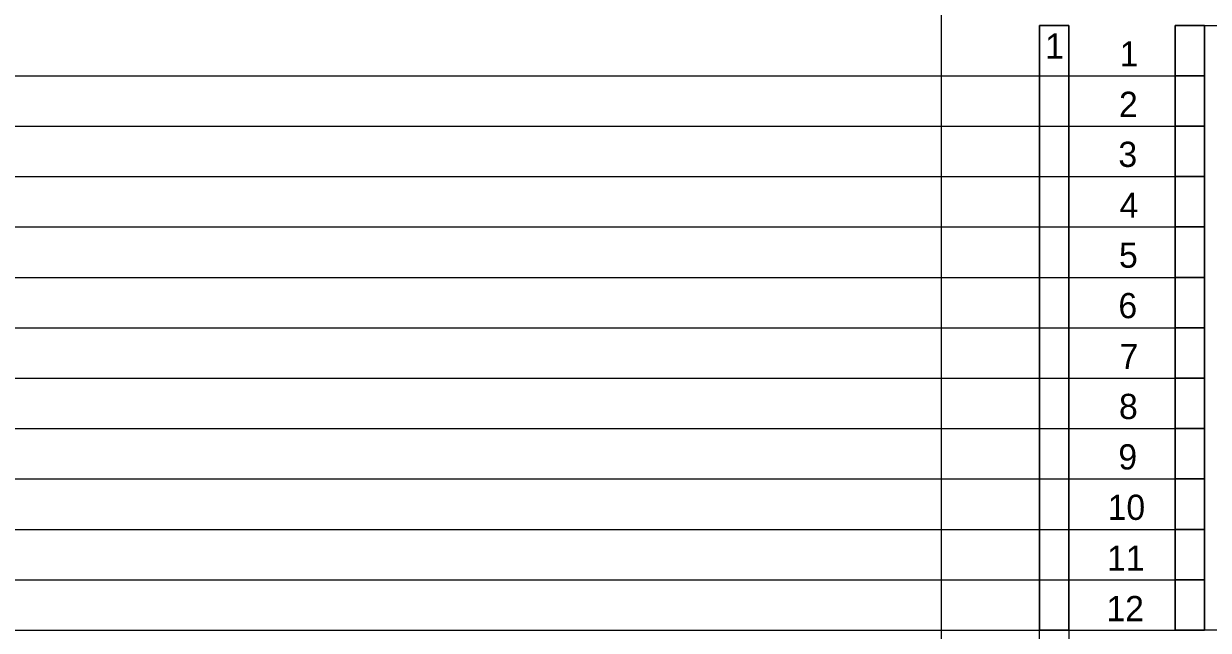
# Model space of a CAD drawing. Extents: x 1901 to 2519, y -3585 to -3154.
# Drawn here: x 2166.7 to 2249.4, y -3245.2 to -3202.9 of the extents above; entities that cross this region are included whole.
import ezdxf

# ---------------------------------------------------------------- set-up
doc = ezdxf.new("R2010")
doc.units = 0
doc.layers.add('rozvláknění', color=7, linetype='Continuous')

msp = doc.modelspace()

# ---------------------------------------------------------------- linework, layer by layer
at = {"layer": 'rozvláknění'}
for p, q in [((2115.435, -3206.527), (2247.063, -3206.526)), ((2115.435, -3210.045), (2247.063, -3210.044)), ((2115.435, -3213.563), (2247.063, -3213.562)), ((2115.435, -3217.081), (2247.063, -3217.08)), ((2115.435, -3220.599), (2247.063, -3220.598)), ((2115.435, -3224.117), (2247.063, -3224.117)), ((2115.435, -3227.636), (2247.063, -3227.635)), ((2115.435, -3231.154), (2247.063, -3231.153)), ((2115.435, -3234.672), (2247.063, -3234.671)), ((2115.435, -3238.19), (2247.063, -3238.189)), ((2115.435, -3241.708), (2247.063, -3241.708)), ((2115.435, -3245.227), (2247.063, -3245.226))]:
    msp.add_line(p, q, dxfattribs=at)
for points in [[(2230.76, -3165.344), (2269.157, -3165.343), (2269.157, -3379.277), (2230.76, -3379.277)], [(2239.641, -3287.48), (2237.6, -3287.48), (2237.6, -3203.007), (2239.641, -3203.007)], [(2239.641, -3245.226), (2237.6, -3245.226), (2237.6, -3203.007), (2239.641, -3203.007)], [(2247.063, -3203.007), (2249.104, -3203.007), (2249.104, -3206.526), (2247.063, -3206.526)], [(2247.063, -3203.007), (2249.104, -3203.007), (2249.104, -3206.526), (2247.063, -3206.526)], [(2249.104, -3203.007), (2251.891, -3203.007), (2251.891, -3245.222), (2249.104, -3245.222)], [(2247.063, -3206.526), (2249.104, -3206.526), (2249.104, -3210.044), (2247.063, -3210.044)], [(2247.063, -3206.526), (2249.104, -3206.526), (2249.104, -3210.044), (2247.063, -3210.044)], [(2247.063, -3210.044), (2249.104, -3210.044), (2249.104, -3213.562), (2247.063, -3213.562)], [(2247.063, -3210.044), (2249.104, -3210.044), (2249.104, -3213.562), (2247.063, -3213.562)], [(2247.063, -3213.562), (2249.104, -3213.562), (2249.104, -3217.08), (2247.063, -3217.08)], [(2247.063, -3213.562), (2249.104, -3213.562), (2249.104, -3217.08), (2247.063, -3217.08)], [(2247.063, -3217.08), (2249.104, -3217.08), (2249.104, -3220.598), (2247.063, -3220.598)], [(2247.063, -3217.08), (2249.104, -3217.08), (2249.104, -3220.598), (2247.063, -3220.598)], [(2247.063, -3220.598), (2249.104, -3220.598), (2249.104, -3224.117), (2247.063, -3224.117)], [(2247.063, -3220.598), (2249.104, -3220.598), (2249.104, -3224.117), (2247.063, -3224.117)], [(2247.063, -3224.117), (2249.104, -3224.117), (2249.104, -3227.635), (2247.063, -3227.635)], [(2247.063, -3224.117), (2249.104, -3224.117), (2249.104, -3227.635), (2247.063, -3227.635)], [(2247.063, -3227.635), (2249.104, -3227.635), (2249.104, -3231.153), (2247.063, -3231.153)], [(2247.063, -3227.635), (2249.104, -3227.635), (2249.104, -3231.153), (2247.063, -3231.153)], [(2247.063, -3231.153), (2249.104, -3231.153), (2249.104, -3234.671), (2247.063, -3234.671)], [(2247.063, -3231.153), (2249.104, -3231.153), (2249.104, -3234.671), (2247.063, -3234.671)], [(2247.063, -3234.671), (2249.104, -3234.671), (2249.104, -3238.189), (2247.063, -3238.189)], [(2247.063, -3234.671), (2249.104, -3234.671), (2249.104, -3238.189), (2247.063, -3238.189)], [(2247.063, -3238.189), (2249.104, -3238.189), (2249.104, -3241.708), (2247.063, -3241.708)], [(2247.063, -3238.189), (2249.104, -3238.189), (2249.104, -3241.708), (2247.063, -3241.708)], [(2247.063, -3241.708), (2249.104, -3241.708), (2249.104, -3245.226), (2247.063, -3245.226)], [(2247.063, -3241.708), (2249.104, -3241.708), (2249.104, -3245.226), (2247.063, -3245.226)]]:
    msp.add_lwpolyline(points, close=True, dxfattribs=at)
for points in [[(2239.641, -3203.007), (2237.6, -3203.007), (2237.6, -3245.226), (2239.641, -3245.226), (2239.641, -3203.007)], [(2239.641, -3203.007), (2237.6, -3203.007), (2237.6, -3245.226), (2239.641, -3245.226), (2239.641, -3203.007)], [(2239.641, -3203.007), (2237.6, -3203.007), (2237.6, -3245.226), (2239.641, -3245.226), (2239.641, -3203.007)], [(2239.641, -3203.007), (2237.6, -3203.007), (2237.6, -3245.226), (2239.641, -3245.226), (2239.641, -3203.007)], [(2239.641, -3203.007), (2237.6, -3203.007), (2237.6, -3245.226), (2239.641, -3245.226), (2239.641, -3203.007)], [(2239.641, -3203.007), (2237.6, -3203.007), (2237.6, -3245.226), (2239.641, -3245.226), (2239.641, -3203.007)], [(2247.063, -3206.526), (2249.104, -3206.526), (2249.104, -3203.007), (2247.063, -3203.007), (2247.063, -3206.526)], [(2247.063, -3206.526), (2249.104, -3206.526), (2249.104, -3203.007), (2247.063, -3203.007), (2247.063, -3206.526)], [(2247.063, -3206.526), (2249.104, -3206.526), (2249.104, -3203.007), (2247.063, -3203.007), (2247.063, -3206.526)], [(2247.063, -3206.526), (2249.104, -3206.526), (2249.104, -3203.007), (2247.063, -3203.007), (2247.063, -3206.526)], [(2247.063, -3206.526), (2249.104, -3206.526), (2249.104, -3203.007), (2247.063, -3203.007), (2247.063, -3206.526)], [(2247.063, -3206.526), (2249.104, -3206.526), (2249.104, -3203.007), (2247.063, -3203.007), (2247.063, -3206.526)], [(2247.063, -3206.526), (2249.104, -3206.526), (2249.104, -3203.007), (2247.063, -3203.007), (2247.063, -3206.526)], [(2247.063, -3206.526), (2249.104, -3206.526), (2249.104, -3203.007), (2247.063, -3203.007), (2247.063, -3206.526)], [(2247.063, -3206.526), (2249.104, -3206.526), (2249.104, -3203.007), (2247.063, -3203.007), (2247.063, -3206.526)], [(2247.063, -3206.526), (2249.104, -3206.526), (2249.104, -3203.007), (2247.063, -3203.007), (2247.063, -3206.526)], [(2247.063, -3210.044), (2249.104, -3210.044), (2249.104, -3206.526), (2247.063, -3206.526), (2247.063, -3210.044)], [(2247.063, -3210.044), (2249.104, -3210.044), (2249.104, -3206.526), (2247.063, -3206.526), (2247.063, -3210.044)], [(2247.063, -3210.044), (2249.104, -3210.044), (2249.104, -3206.526), (2247.063, -3206.526), (2247.063, -3210.044)], [(2247.063, -3210.044), (2249.104, -3210.044), (2249.104, -3206.526), (2247.063, -3206.526), (2247.063, -3210.044)], [(2247.063, -3210.044), (2249.104, -3210.044), (2249.104, -3206.526), (2247.063, -3206.526), (2247.063, -3210.044)], [(2247.063, -3210.044), (2249.104, -3210.044), (2249.104, -3206.526), (2247.063, -3206.526), (2247.063, -3210.044)], [(2247.063, -3210.044), (2249.104, -3210.044), (2249.104, -3206.526), (2247.063, -3206.526), (2247.063, -3210.044)], [(2247.063, -3210.044), (2249.104, -3210.044), (2249.104, -3206.526), (2247.063, -3206.526), (2247.063, -3210.044)], [(2247.063, -3210.044), (2249.104, -3210.044), (2249.104, -3206.526), (2247.063, -3206.526), (2247.063, -3210.044)], [(2247.063, -3210.044), (2249.104, -3210.044), (2249.104, -3206.526), (2247.063, -3206.526), (2247.063, -3210.044)], [(2247.063, -3213.562), (2249.104, -3213.562), (2249.104, -3210.044), (2247.063, -3210.044), (2247.063, -3213.562)], [(2247.063, -3213.562), (2249.104, -3213.562), (2249.104, -3210.044), (2247.063, -3210.044), (2247.063, -3213.562)], [(2247.063, -3213.562), (2249.104, -3213.562), (2249.104, -3210.044), (2247.063, -3210.044), (2247.063, -3213.562)], [(2247.063, -3213.562), (2249.104, -3213.562), (2249.104, -3210.044), (2247.063, -3210.044), (2247.063, -3213.562)], [(2247.063, -3213.562), (2249.104, -3213.562), (2249.104, -3210.044), (2247.063, -3210.044), (2247.063, -3213.562)], [(2247.063, -3213.562), (2249.104, -3213.562), (2249.104, -3210.044), (2247.063, -3210.044), (2247.063, -3213.562)], [(2247.063, -3213.562), (2249.104, -3213.562), (2249.104, -3210.044), (2247.063, -3210.044), (2247.063, -3213.562)], [(2247.063, -3213.562), (2249.104, -3213.562), (2249.104, -3210.044), (2247.063, -3210.044), (2247.063, -3213.562)], [(2247.063, -3213.562), (2249.104, -3213.562), (2249.104, -3210.044), (2247.063, -3210.044), (2247.063, -3213.562)], [(2247.063, -3213.562), (2249.104, -3213.562), (2249.104, -3210.044), (2247.063, -3210.044), (2247.063, -3213.562)], [(2247.063, -3217.08), (2249.104, -3217.08), (2249.104, -3213.562), (2247.063, -3213.562), (2247.063, -3217.08)], [(2247.063, -3217.08), (2249.104, -3217.08), (2249.104, -3213.562), (2247.063, -3213.562), (2247.063, -3217.08)], [(2247.063, -3217.08), (2249.104, -3217.08), (2249.104, -3213.562), (2247.063, -3213.562), (2247.063, -3217.08)], [(2247.063, -3217.08), (2249.104, -3217.08), (2249.104, -3213.562), (2247.063, -3213.562), (2247.063, -3217.08)], [(2247.063, -3217.08), (2249.104, -3217.08), (2249.104, -3213.562), (2247.063, -3213.562), (2247.063, -3217.08)], [(2247.063, -3217.08), (2249.104, -3217.08), (2249.104, -3213.562), (2247.063, -3213.562), (2247.063, -3217.08)], [(2247.063, -3217.08), (2249.104, -3217.08), (2249.104, -3213.562), (2247.063, -3213.562), (2247.063, -3217.08)], [(2247.063, -3217.08), (2249.104, -3217.08), (2249.104, -3213.562), (2247.063, -3213.562), (2247.063, -3217.08)], [(2247.063, -3217.08), (2249.104, -3217.08), (2249.104, -3213.562), (2247.063, -3213.562), (2247.063, -3217.08)], [(2247.063, -3217.08), (2249.104, -3217.08), (2249.104, -3213.562), (2247.063, -3213.562), (2247.063, -3217.08)], [(2247.063, -3220.598), (2249.104, -3220.598), (2249.104, -3217.08), (2247.063, -3217.08), (2247.063, -3220.598)], [(2247.063, -3220.598), (2249.104, -3220.598), (2249.104, -3217.08), (2247.063, -3217.08), (2247.063, -3220.598)], [(2247.063, -3220.598), (2249.104, -3220.598), (2249.104, -3217.08), (2247.063, -3217.08), (2247.063, -3220.598)], [(2247.063, -3220.598), (2249.104, -3220.598), (2249.104, -3217.08), (2247.063, -3217.08), (2247.063, -3220.598)], [(2247.063, -3220.598), (2249.104, -3220.598), (2249.104, -3217.08), (2247.063, -3217.08), (2247.063, -3220.598)], [(2247.063, -3220.598), (2249.104, -3220.598), (2249.104, -3217.08), (2247.063, -3217.08), (2247.063, -3220.598)], [(2247.063, -3220.598), (2249.104, -3220.598), (2249.104, -3217.08), (2247.063, -3217.08), (2247.063, -3220.598)], [(2247.063, -3220.598), (2249.104, -3220.598), (2249.104, -3217.08), (2247.063, -3217.08), (2247.063, -3220.598)], [(2247.063, -3220.598), (2249.104, -3220.598), (2249.104, -3217.08), (2247.063, -3217.08), (2247.063, -3220.598)], [(2247.063, -3220.598), (2249.104, -3220.598), (2249.104, -3217.08), (2247.063, -3217.08), (2247.063, -3220.598)], [(2247.063, -3224.117), (2249.104, -3224.117), (2249.104, -3220.598), (2247.063, -3220.598), (2247.063, -3224.117)], [(2247.063, -3224.117), (2249.104, -3224.117), (2249.104, -3220.598), (2247.063, -3220.598), (2247.063, -3224.117)], [(2247.063, -3224.117), (2249.104, -3224.117), (2249.104, -3220.598), (2247.063, -3220.598), (2247.063, -3224.117)], [(2247.063, -3224.117), (2249.104, -3224.117), (2249.104, -3220.598), (2247.063, -3220.598), (2247.063, -3224.117)], [(2247.063, -3224.117), (2249.104, -3224.117), (2249.104, -3220.598), (2247.063, -3220.598), (2247.063, -3224.117)], [(2247.063, -3224.117), (2249.104, -3224.117), (2249.104, -3220.598), (2247.063, -3220.598), (2247.063, -3224.117)], [(2247.063, -3224.117), (2249.104, -3224.117), (2249.104, -3220.598), (2247.063, -3220.598), (2247.063, -3224.117)], [(2247.063, -3224.117), (2249.104, -3224.117), (2249.104, -3220.598), (2247.063, -3220.598), (2247.063, -3224.117)], [(2247.063, -3224.117), (2249.104, -3224.117), (2249.104, -3220.598), (2247.063, -3220.598), (2247.063, -3224.117)], [(2247.063, -3224.117), (2249.104, -3224.117), (2249.104, -3220.598), (2247.063, -3220.598), (2247.063, -3224.117)], [(2247.063, -3227.635), (2249.104, -3227.635), (2249.104, -3224.117), (2247.063, -3224.117), (2247.063, -3227.635)], [(2247.063, -3227.635), (2249.104, -3227.635), (2249.104, -3224.117), (2247.063, -3224.117), (2247.063, -3227.635)], [(2247.063, -3227.635), (2249.104, -3227.635), (2249.104, -3224.117), (2247.063, -3224.117), (2247.063, -3227.635)], [(2247.063, -3227.635), (2249.104, -3227.635), (2249.104, -3224.117), (2247.063, -3224.117), (2247.063, -3227.635)], [(2247.063, -3227.635), (2249.104, -3227.635), (2249.104, -3224.117), (2247.063, -3224.117), (2247.063, -3227.635)], [(2247.063, -3227.635), (2249.104, -3227.635), (2249.104, -3224.117), (2247.063, -3224.117), (2247.063, -3227.635)], [(2247.063, -3227.635), (2249.104, -3227.635), (2249.104, -3224.117), (2247.063, -3224.117), (2247.063, -3227.635)], [(2247.063, -3227.635), (2249.104, -3227.635), (2249.104, -3224.117), (2247.063, -3224.117), (2247.063, -3227.635)], [(2247.063, -3227.635), (2249.104, -3227.635), (2249.104, -3224.117), (2247.063, -3224.117), (2247.063, -3227.635)], [(2247.063, -3227.635), (2249.104, -3227.635), (2249.104, -3224.117), (2247.063, -3224.117), (2247.063, -3227.635)], [(2247.063, -3231.153), (2249.104, -3231.153), (2249.104, -3227.635), (2247.063, -3227.635), (2247.063, -3231.153)], [(2247.063, -3231.153), (2249.104, -3231.153), (2249.104, -3227.635), (2247.063, -3227.635), (2247.063, -3231.153)], [(2247.063, -3231.153), (2249.104, -3231.153), (2249.104, -3227.635), (2247.063, -3227.635), (2247.063, -3231.153)], [(2247.063, -3231.153), (2249.104, -3231.153), (2249.104, -3227.635), (2247.063, -3227.635), (2247.063, -3231.153)], [(2247.063, -3231.153), (2249.104, -3231.153), (2249.104, -3227.635), (2247.063, -3227.635), (2247.063, -3231.153)], [(2247.063, -3231.153), (2249.104, -3231.153), (2249.104, -3227.635), (2247.063, -3227.635), (2247.063, -3231.153)], [(2247.063, -3231.153), (2249.104, -3231.153), (2249.104, -3227.635), (2247.063, -3227.635), (2247.063, -3231.153)], [(2247.063, -3231.153), (2249.104, -3231.153), (2249.104, -3227.635), (2247.063, -3227.635), (2247.063, -3231.153)], [(2247.063, -3231.153), (2249.104, -3231.153), (2249.104, -3227.635), (2247.063, -3227.635), (2247.063, -3231.153)], [(2247.063, -3231.153), (2249.104, -3231.153), (2249.104, -3227.635), (2247.063, -3227.635), (2247.063, -3231.153)], [(2247.063, -3234.671), (2249.104, -3234.671), (2249.104, -3231.153), (2247.063, -3231.153), (2247.063, -3234.671)], [(2247.063, -3234.671), (2249.104, -3234.671), (2249.104, -3231.153), (2247.063, -3231.153), (2247.063, -3234.671)], [(2247.063, -3234.671), (2249.104, -3234.671), (2249.104, -3231.153), (2247.063, -3231.153), (2247.063, -3234.671)], [(2247.063, -3234.671), (2249.104, -3234.671), (2249.104, -3231.153), (2247.063, -3231.153), (2247.063, -3234.671)], [(2247.063, -3234.671), (2249.104, -3234.671), (2249.104, -3231.153), (2247.063, -3231.153), (2247.063, -3234.671)], [(2247.063, -3234.671), (2249.104, -3234.671), (2249.104, -3231.153), (2247.063, -3231.153), (2247.063, -3234.671)], [(2247.063, -3234.671), (2249.104, -3234.671), (2249.104, -3231.153), (2247.063, -3231.153), (2247.063, -3234.671)], [(2247.063, -3234.671), (2249.104, -3234.671), (2249.104, -3231.153), (2247.063, -3231.153), (2247.063, -3234.671)], [(2247.063, -3234.671), (2249.104, -3234.671), (2249.104, -3231.153), (2247.063, -3231.153), (2247.063, -3234.671)], [(2247.063, -3234.671), (2249.104, -3234.671), (2249.104, -3231.153), (2247.063, -3231.153), (2247.063, -3234.671)], [(2247.063, -3238.189), (2249.104, -3238.189), (2249.104, -3234.671), (2247.063, -3234.671), (2247.063, -3238.189)], [(2247.063, -3238.189), (2249.104, -3238.189), (2249.104, -3234.671), (2247.063, -3234.671), (2247.063, -3238.189)], [(2247.063, -3238.189), (2249.104, -3238.189), (2249.104, -3234.671), (2247.063, -3234.671), (2247.063, -3238.189)], [(2247.063, -3238.189), (2249.104, -3238.189), (2249.104, -3234.671), (2247.063, -3234.671), (2247.063, -3238.189)], [(2247.063, -3238.189), (2249.104, -3238.189), (2249.104, -3234.671), (2247.063, -3234.671), (2247.063, -3238.189)], [(2247.063, -3238.189), (2249.104, -3238.189), (2249.104, -3234.671), (2247.063, -3234.671), (2247.063, -3238.189)], [(2247.063, -3238.189), (2249.104, -3238.189), (2249.104, -3234.671), (2247.063, -3234.671), (2247.063, -3238.189)], [(2247.063, -3238.189), (2249.104, -3238.189), (2249.104, -3234.671), (2247.063, -3234.671), (2247.063, -3238.189)], [(2247.063, -3238.189), (2249.104, -3238.189), (2249.104, -3234.671), (2247.063, -3234.671), (2247.063, -3238.189)], [(2247.063, -3238.189), (2249.104, -3238.189), (2249.104, -3234.671), (2247.063, -3234.671), (2247.063, -3238.189)], [(2247.063, -3241.708), (2249.104, -3241.708), (2249.104, -3238.189), (2247.063, -3238.189), (2247.063, -3241.708)], [(2247.063, -3241.708), (2249.104, -3241.708), (2249.104, -3238.189), (2247.063, -3238.189), (2247.063, -3241.708)], [(2247.063, -3241.708), (2249.104, -3241.708), (2249.104, -3238.189), (2247.063, -3238.189), (2247.063, -3241.708)], [(2247.063, -3241.708), (2249.104, -3241.708), (2249.104, -3238.189), (2247.063, -3238.189), (2247.063, -3241.708)], [(2247.063, -3241.708), (2249.104, -3241.708), (2249.104, -3238.189), (2247.063, -3238.189), (2247.063, -3241.708)], [(2247.063, -3241.708), (2249.104, -3241.708), (2249.104, -3238.189), (2247.063, -3238.189), (2247.063, -3241.708)], [(2247.063, -3241.708), (2249.104, -3241.708), (2249.104, -3238.189), (2247.063, -3238.189), (2247.063, -3241.708)], [(2247.063, -3241.708), (2249.104, -3241.708), (2249.104, -3238.189), (2247.063, -3238.189), (2247.063, -3241.708)], [(2247.063, -3241.708), (2249.104, -3241.708), (2249.104, -3238.189), (2247.063, -3238.189), (2247.063, -3241.708)], [(2247.063, -3241.708), (2249.104, -3241.708), (2249.104, -3238.189), (2247.063, -3238.189), (2247.063, -3241.708)], [(2247.063, -3245.226), (2249.104, -3245.226), (2249.104, -3241.708), (2247.063, -3241.708), (2247.063, -3245.226)], [(2247.063, -3245.226), (2249.104, -3245.226), (2249.104, -3241.708), (2247.063, -3241.708), (2247.063, -3245.226)], [(2247.063, -3245.226), (2249.104, -3245.226), (2249.104, -3241.708), (2247.063, -3241.708), (2247.063, -3245.226)], [(2247.063, -3245.226), (2249.104, -3245.226), (2249.104, -3241.708), (2247.063, -3241.708), (2247.063, -3245.226)], [(2247.063, -3245.226), (2249.104, -3245.226), (2249.104, -3241.708), (2247.063, -3241.708), (2247.063, -3245.226)], [(2247.063, -3245.226), (2249.104, -3245.226), (2249.104, -3241.708), (2247.063, -3241.708), (2247.063, -3245.226)], [(2247.063, -3245.226), (2249.104, -3245.226), (2249.104, -3241.708), (2247.063, -3241.708), (2247.063, -3245.226)], [(2247.063, -3245.226), (2249.104, -3245.226), (2249.104, -3241.708), (2247.063, -3241.708), (2247.063, -3245.226)], [(2247.063, -3245.226), (2249.104, -3245.226), (2249.104, -3241.708), (2247.063, -3241.708), (2247.063, -3245.226)], [(2247.063, -3245.226), (2249.104, -3245.226), (2249.104, -3241.708), (2247.063, -3241.708), (2247.063, -3245.226)]]:
    msp.add_lwpolyline(points, dxfattribs=at)

# ---------------------------------------------------------------- texts
for s, p in [('1', (2237.998, -3205.333)), ('1', (2237.998, -3205.333)), ('1', (2243.191, -3205.879)), ('2', (2243.145, -3209.399)), ('3', (2243.103, -3212.889)), ('4', (2243.191, -3216.439)), ('5', (2243.145, -3219.929)), ('6', (2243.103, -3223.449)), ('7', (2243.191, -3226.999)), ('8', (2243.145, -3230.489)), ('9', (2243.103, -3234.009)), ('10', (2242.354, -3237.529)), ('11', (2242.308, -3241.079)), ('12', (2242.266, -3244.599))]:
    msp.add_text(s, height=1.76, dxfattribs=at).set_placement(p)

doc.saveas('drawing.dxf')
